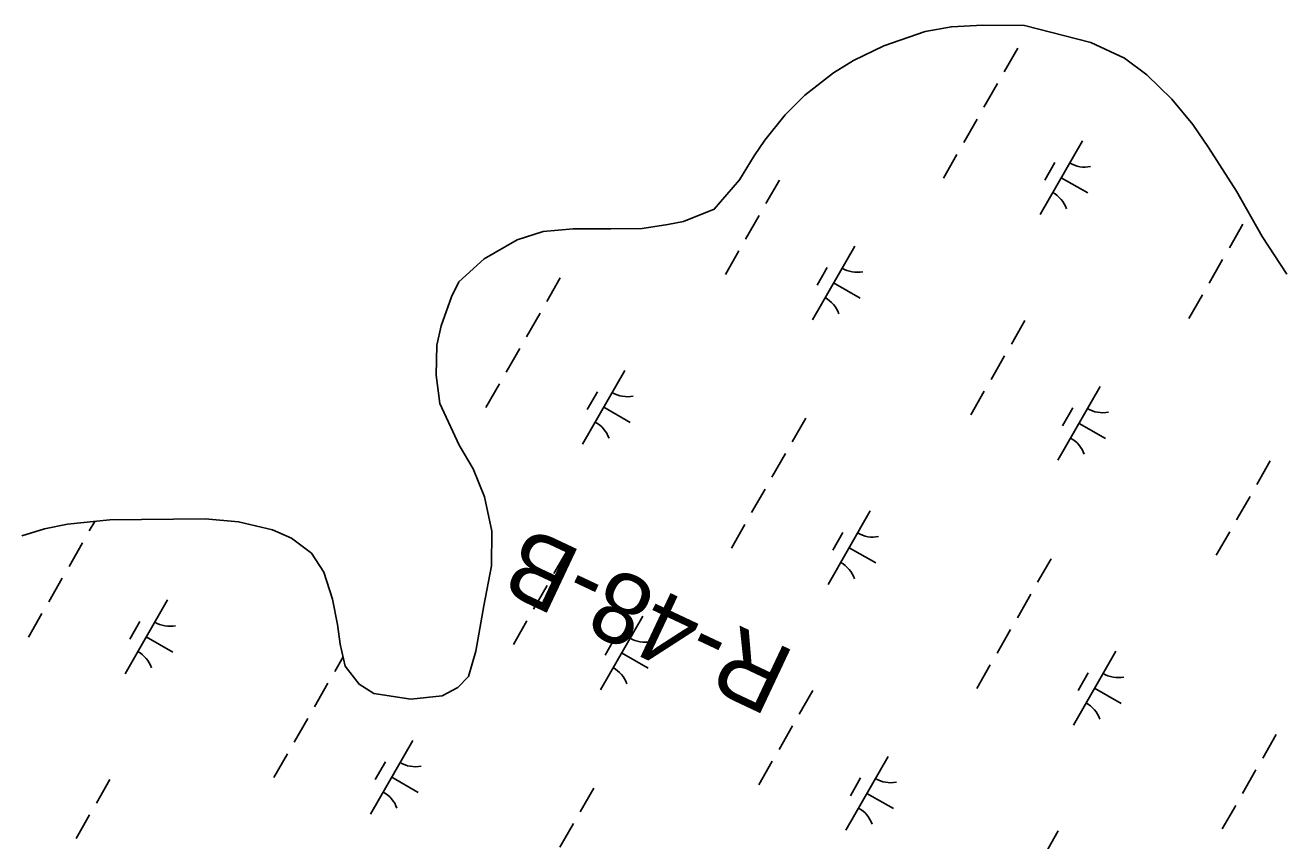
# Model space of a CAD drawing. Extents: x 3930721 to 3950824, y 220441 to 242861.
# Drawn here: x 3937680 to 3938420, y 227205 to 227685 of the extents above; entities that cross this region are included whole.
import ezdxf

# ---------------------------------------------------------------- set-up
doc = ezdxf.new("R2010")
doc.units = 0
for name, color, linetype in [('V-RIVR-RANG-IDEN', 7, 'Continuous'), ('V-TOPO-SHOR', 7, 'Continuous'), ('V-WETL-SWMP', 7, 'Continuous')]:
    doc.layers.add(name, color=color, linetype=linetype)

msp = doc.modelspace()

# ---------------------------------------------------------------- linework, layer by layer
at = {"layer": 'V-TOPO-SHOR'}
for points in [[(3938422.15, 227538.7), (3938407.73, 227560.88), (3938392.53, 227587.61), (3938376.14, 227613.36), (3938366.86, 227626.82), (3938354.61, 227641.87), (3938339.79, 227656.14), (3938326.75, 227665.85), (3938306.97, 227675.18), (3938267.81, 227685.12), (3938243.47, 227685.35), (3938224.87, 227684.39), (3938209.43, 227681.64), (3938185.08, 227673.16), (3938167.27, 227664.48), (3938155.58, 227657.37), (3938138.75, 227644.14), (3938127.06, 227632.48), (3938115.17, 227617.66), (3938108.82, 227608.36), (3938100.29, 227594.33), (3938085.43, 227577.13), (3938067.42, 227569.84), (3938058.12, 227568.07), (3938043.08, 227565.71), (3938024.68, 227565.54), (3938002.51, 227565.37), (3937984.7, 227563.81), (3937969.46, 227559.08), (3937950.06, 227547.83), (3937935.2, 227534.2), (3937930.84, 227525.5), (3937924.88, 227508.29), (3937922.29, 227497.02), (3937921.87, 227479.41), (3937924.03, 227462.58), (3937935.47, 227438.04), (3937943.56, 227424.17), (3937950.27, 227407.74), (3937954.59, 227387.56), (3937954.37, 227367.18), (3937949.99, 227343.64), (3937945.2, 227316.93), (3937940.83, 227301.9), (3937934.69, 227295.58), (3937925.38, 227290.64)], [(3937925.38, 227290.64), (3937906.98, 227288.69), (3937885.22, 227291.88), (3937876.52, 227297.43), (3937868.42, 227308.13), (3937865.47, 227320.99), (3937863.9, 227332.67), (3937860.95, 227347.51), (3937855.83, 227363.35), (3937848.52, 227374.64), (3937836.86, 227383.36), (3937825.59, 227388.32), (3937805.61, 227393.09), (3937786.03, 227394.7), (3937730.03, 227394.18), (3937705.1, 227391.64), (3937691.44, 227388.89), (3937678.18, 227384.76)]]:
    msp.add_lwpolyline(points, dxfattribs=at)
at = {"layer": 'V-WETL-SWMP'}
for p, q in [((3938209.43, 227681.64), (3938185.08, 227673.16)), ((3938224.87, 227684.39), (3938209.43, 227681.64)), ((3938243.47, 227685.35), (3938224.87, 227684.39)), ((3938267.81, 227685.12), (3938243.47, 227685.35)), ((3938306.97, 227675.18), (3938267.81, 227685.12)), ((3938326.74, 227665.85), (3938306.97, 227675.18)), ((3938185.08, 227673.16), (3938167.27, 227664.48)), ((3938263.93, 227671.73), (3938255.98, 227657.85)), ((3938167.27, 227664.48), (3938155.58, 227657.37)), ((3938339.79, 227656.14), (3938326.74, 227665.85)), ((3938155.58, 227657.37), (3938138.75, 227644.14)), ((3938354.61, 227641.87), (3938339.79, 227656.14)), ((3938252.01, 227650.91), (3938244.06, 227637.02)), ((3938138.75, 227644.14), (3938127.06, 227632.48)), ((3938366.86, 227626.82), (3938354.61, 227641.87)), ((3938127.06, 227632.48), (3938115.17, 227617.65)), ((3938240.08, 227630.08), (3938232.13, 227616.2)), ((3938376.14, 227613.35), (3938366.86, 227626.82)), ((3938115.17, 227617.65), (3938108.82, 227608.36)), ((3938301.91, 227617.23), (3938277.06, 227573.84)), ((3938108.82, 227608.36), (3938100.3, 227594.33)), ((3938228.15, 227609.25), (3938220.2, 227595.37)), ((3938392.53, 227587.61), (3938376.14, 227613.35)), ((3938285.77, 227604.58), (3938279.8, 227594.17)), ((3938100.3, 227594.33), (3938085.43, 227577.13)), ((3938123.77, 227594.18), (3938115.82, 227580.3)), ((3938289.48, 227595.54), (3938305.1, 227586.59)), ((3938407.73, 227560.88), (3938392.53, 227587.61)), ((3938085.43, 227577.13), (3938067.42, 227569.84)), ((3938111.84, 227573.36), (3938103.89, 227559.47)), ((3937984.7, 227563.81), (3937969.46, 227559.08)), ((3938002.51, 227565.37), (3937984.7, 227563.81)), ((3938024.67, 227565.54), (3938002.51, 227565.37)), ((3938043.08, 227565.71), (3938024.67, 227565.54)), ((3938058.12, 227568.07), (3938043.08, 227565.71)), ((3938067.42, 227569.84), (3938058.12, 227568.07)), ((3938396.35, 227568.24), (3938388.4, 227554.36)), ((3937969.46, 227559.08), (3937950.06, 227547.83)), ((3938422.14, 227538.7), (3938407.73, 227560.88)), ((3938099.92, 227552.53), (3938091.96, 227538.65)), ((3938168.04, 227555.34), (3938143.19, 227511.95)), ((3937950.06, 227547.83), (3937935.2, 227534.2)), ((3938151.9, 227542.69), (3938145.94, 227532.28)), ((3938384.42, 227547.41), (3938376.47, 227533.53)), ((3937935.2, 227534.2), (3937930.84, 227525.5)), ((3937994.87, 227536.63), (3937986.92, 227522.75)), ((3938155.61, 227533.65), (3938171.23, 227524.7)), ((3938372.49, 227526.59), (3938364.54, 227512.7)), ((3937930.84, 227525.5), (3937924.88, 227508.29)), ((3937982.95, 227515.8), (3937974.99, 227501.92)), ((3938268.11, 227511.52), (3938260.16, 227497.63)), ((3937924.88, 227508.29), (3937922.29, 227497.02)), ((3937922.29, 227497.02), (3937921.87, 227479.41)), ((3937971.02, 227494.98), (3937963.07, 227481.09)), ((3938256.19, 227490.69), (3938248.23, 227476.81)), ((3938032.85, 227482.13), (3938008, 227438.74)), ((3937921.87, 227479.41), (3937924.03, 227462.59)), ((3937959.09, 227474.15), (3937951.14, 227460.27)), ((3938016.71, 227469.48), (3938010.74, 227459.06)), ((3938244.26, 227469.86), (3938236.31, 227455.98)), ((3938312.38, 227472.68), (3938287.53, 227429.29)), ((3937924.03, 227462.59), (3937935.47, 227438.04)), ((3938020.42, 227460.44), (3938036.04, 227451.49)), ((3938296.24, 227460.02), (3938290.28, 227449.61)), ((3938139.22, 227453.96), (3938131.26, 227440.08)), ((3938299.96, 227450.98), (3938315.58, 227442.04)), ((3937935.47, 227438.04), (3937943.56, 227424.17)), ((3938127.29, 227433.14), (3938119.34, 227419.25)), ((3937943.56, 227424.17), (3937950.27, 227407.74)), ((3938412.45, 227428.85), (3938404.5, 227414.97)), ((3938115.36, 227412.31), (3938107.41, 227398.43)), ((3938400.53, 227408.02), (3938392.58, 227394.14)), ((3937950.27, 227407.74), (3937954.59, 227387.56)), ((3937730.03, 227394.18), (3937705.1, 227391.64)), ((3937721.09, 227393.27), (3937717.86, 227387.64)), ((3937786.03, 227394.7), (3937730.03, 227394.18)), ((3937805.61, 227393.09), (3937786.03, 227394.7)), ((3937825.59, 227388.32), (3937805.61, 227393.09)), ((3938177.19, 227399.46), (3938152.34, 227356.08)), ((3937691.44, 227388.89), (3937678.18, 227384.75)), ((3937705.1, 227391.64), (3937691.44, 227388.89)), ((3937836.86, 227383.36), (3937825.59, 227388.32)), ((3937954.59, 227387.56), (3937954.37, 227367.18)), ((3938103.43, 227391.49), (3938095.48, 227377.6)), ((3938161.05, 227386.81), (3938155.09, 227376.4)), ((3938388.6, 227387.2), (3938380.65, 227373.31)), ((3937713.89, 227380.7), (3937705.93, 227366.82)), ((3937848.52, 227374.64), (3937836.86, 227383.36)), ((3937855.83, 227363.35), (3937848.52, 227374.64)), ((3937999.05, 227376.41), (3937991.1, 227362.53)), ((3938164.76, 227377.77), (3938180.38, 227368.82)), ((3938283.56, 227371.3), (3938275.61, 227357.41)), ((3937954.37, 227367.18), (3937949.99, 227343.64)), ((3937701.96, 227359.88), (3937694.01, 227345.99)), ((3937860.95, 227347.51), (3937855.83, 227363.35)), ((3937987.13, 227355.59), (3937979.17, 227341.7)), ((3938271.63, 227350.47), (3938263.68, 227336.59)), ((3937763.79, 227347.03), (3937738.94, 227303.64)), ((3937863.9, 227332.67), (3937860.95, 227347.51)), ((3937949.99, 227343.64), (3937945.2, 227316.93)), ((3937690.03, 227339.05), (3937682.08, 227325.17)), ((3937747.65, 227334.38), (3937741.68, 227323.96)), ((3937975.2, 227334.76), (3937967.25, 227320.88)), ((3938043.32, 227337.57), (3938018.47, 227294.19)), ((3937865.47, 227320.99), (3937863.9, 227332.67)), ((3938259.7, 227329.65), (3938251.75, 227315.76)), ((3937751.36, 227325.33), (3937766.98, 227316.39)), ((3937868.42, 227308.13), (3937865.47, 227320.99)), ((3938027.18, 227324.92), (3938021.22, 227314.51)), ((3937867.16, 227313.63), (3937862.2, 227304.98)), ((3937945.2, 227316.93), (3937940.83, 227301.9)), ((3938030.9, 227315.88), (3938046.51, 227306.93)), ((3938321.53, 227316.8), (3938296.68, 227273.41)), ((3937876.52, 227297.43), (3937868.42, 227308.13)), ((3938247.77, 227308.82), (3938239.82, 227294.94)), ((3937858.23, 227298.04), (3937850.28, 227284.15)), ((3937885.22, 227291.88), (3937876.52, 227297.43)), ((3937940.83, 227301.9), (3937934.69, 227295.58)), ((3938305.39, 227304.15), (3938299.43, 227293.73)), ((3937906.98, 227288.69), (3937885.22, 227291.88)), ((3937925.38, 227290.64), (3937906.98, 227288.69)), ((3937934.69, 227295.58), (3937925.38, 227290.64)), ((3938143.39, 227293.75), (3938135.44, 227279.86)), ((3938309.1, 227295.1), (3938324.72, 227286.16)), ((3937846.3, 227277.21), (3937838.35, 227263.33)), ((3938131.47, 227272.92), (3938123.51, 227259.04)), ((3938415.97, 227267.81), (3938408.02, 227253.92)), ((3937908.13, 227264.36), (3937883.28, 227220.97)), ((3937834.37, 227256.38), (3937826.42, 227242.5)), ((3938187.66, 227254.91), (3938162.81, 227211.52)), ((3937891.99, 227251.71), (3937886.03, 227241.3)), ((3938119.54, 227252.09), (3938111.59, 227238.21)), ((3938404.04, 227246.98), (3938396.09, 227233.1)), ((3937729.99, 227241.31), (3937722.04, 227227.43)), ((3937895.7, 227242.67), (3937911.32, 227233.72)), ((3938171.52, 227242.25), (3938165.56, 227231.84)), ((3938014.5, 227236.2), (3938006.55, 227222.31)), ((3938175.24, 227233.21), (3938190.86, 227224.27)), ((3938392.12, 227226.15), (3938384.16, 227212.27)), ((3937718.06, 227220.48), (3937710.11, 227206.6)), ((3938002.57, 227215.37), (3937994.62, 227201.49)), ((3938287.74, 227211.08), (3938279.78, 227197.2))]:
    msp.add_line(p, q, dxfattribs=at)
for centre, start, end in [((3938303.41, 227619.39), 239.42788, 280.97154), ((3938275.96, 227571.45), 19.42788, 60.97154), ((3938169.55, 227557.5), 239.42788, 280.97154), ((3938142.09, 227509.56), 19.42788, 60.97154), ((3938034.35, 227484.29), 239.42788, 280.97154), ((3938313.89, 227474.83), 239.42788, 280.97154), ((3938006.9, 227436.35), 19.42788, 60.97154), ((3938286.43, 227426.89), 19.42788, 60.97154), ((3938178.7, 227401.62), 239.42788, 280.97154), ((3938151.24, 227353.68), 19.42788, 60.97154), ((3937765.29, 227349.19), 239.42788, 280.97154), ((3938044.83, 227339.73), 239.42788, 280.97154), ((3937737.84, 227301.25), 19.42788, 60.97154), ((3938017.37, 227291.79), 19.42788, 60.97154), ((3938323.04, 227318.96), 239.42788, 280.97154), ((3938295.58, 227271.02), 19.42788, 60.97154), ((3937909.64, 227266.52), 239.42788, 280.97154), ((3938189.17, 227257.06), 239.42788, 280.97154), ((3937882.18, 227218.58), 19.42788, 60.97154), ((3938161.72, 227209.13), 19.42788, 60.97154)]:
    msp.add_arc(centre, 17.62, start, end, dxfattribs=at)

# ---------------------------------------------------------------- texts
at = {"layer": 'V-RIVR-RANG-IDEN'}
msp.add_text('R-48-B', height=41.5, rotation=154.78563, dxfattribs=at).set_placement((3938134.26, 227315.99))

doc.saveas('drawing.dxf')
